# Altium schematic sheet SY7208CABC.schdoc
size 127 x 101 mm
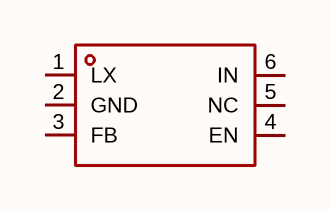
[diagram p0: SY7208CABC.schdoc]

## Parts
U?  sy7208cabc  [TSOT-23-6_L2.9-W1.6-P0.95-LS2.8-BR]  (value not drawn)

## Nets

Not connected (* = marked no-connect by the designer): U? 1(LX) 2(GND) 3(FB) 4(EN) 5(NC) 6(IN)

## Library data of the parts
U? = sy7208cabc: 功能类型:升压型;工作电压:3V~25V;输出电压:-;输出电流:-;输出类型:可调;; Manufacturer: Silergy(矽力杰); AddInBom: yes; ModelId: 2c4039b5b88644c1bda4b4ba9e971667; ModelName: TSOT-23-6_L2.9-W1.6-H1.1-LS2.8-P0.95; ModelTransform: 110.45568,114.173,0,180,0,0,-0.005,-0.0005,0; Function: 升压型; Voltage - Supply: 3V~25V; Frequency - Switching: 1MHz; Synchronous Rectifier: 否; Number of Outputs: 1; Topology: 升压式; Quiescent Current: 100uA; Switch tube (built-in/external): 内置; Output Type: 可调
